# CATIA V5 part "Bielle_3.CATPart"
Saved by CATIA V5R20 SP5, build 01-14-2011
Part number: Bielle_3
Publications: "Diametre_ext_1", "Diametre_int_1", "Diametre_int_2", "Diametre_ext_2"
Bounding box of the stored display mesh (mm): x 70.871 to 97.557, y -48.79 to -20.435, z 3 to 6
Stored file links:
  D:\thinkmotion-MPB\Dropbox\IAO_2011\MMS_GR3\IAO_2011_1523_mkessler\mkessler\mkessler_IAO\mkessler_INIT\Bielle_3.CATPart
  C:\Users\MARLENE\Documents\IFMA\S3\IAO\Copie de CAO\Assemblage_final.CATProduct
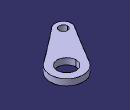
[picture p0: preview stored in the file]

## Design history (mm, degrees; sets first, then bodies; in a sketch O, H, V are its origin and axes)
Parameters
  Diametre_ext_1 = 16 mm
  Diametre_int_1 = 9 mm
  Diametre_int_2 = 4 mm
  Diametre_ext_2 = 8 mm
Set1
  Plane1: linked copy from another document
  Point1: linked copy from another document
  Point2: linked copy from another document
  Plane2: linked copy from another document
Set2
  Plane3: stored without definition
Body1 (main body)
  Sketch1 on Plane2, origin (0, 0, 3), H (1, 0, 0), V (0, 1, 0)
    circle A1 centre (74.862, -44.7925) radius 2
    reference projected point E1 (74.862, -44.7925) from Point1
    arc A2 centre (74.862, -44.7925) radius 4 from (71.9981, -42) to (77.9443, -47.3419) ccw
    reference projected point E2 (74.862, -44.7925) from Point1
    circle A3 centre (89.5645, -28.4268) radius 4.5
    reference projected point E3 (89.5645, -28.4268) from Point2
    arc A4 centre (89.5645, -28.4268) radius 8 from (93.7435, -35.2485) to (82.3356, -25) ccw
    reference projected point E4 (89.5645, -28.4268) from Point2
    line L1 (71.9981, -42) -> (82.3356, -25)
    point P5 (71.9981, -42)
    point P6 (82.3356, -25)
    axis line L2 (89.5645, -28.4268) -> (74.862, -44.7925)
    point P7 (93.7435, -35.2485)
    point P8 (77.9443, -47.3419)
    line L3 (77.9443, -47.3419) -> (93.7435, -35.2485)
    radius A4 = 8 {= Diametre_ext_1 /2}
    radius A3 = 4.5 {= Diametre_int_1 /2}
    radius A2 = 4 {= Diametre_ext_2 /2}
    radius A2 = 4 (reference)
    radius A1 = 2 {= Diametre_int_2 /2}
    concentricity: E1 A1, A2 E2, E3 A3, E4 A4
    symmetry: P6 P7 L2, P5 P8 L2, L1 L3 L2
  Pad1: profile Sketch1, direction (0, 0, 1), length 3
